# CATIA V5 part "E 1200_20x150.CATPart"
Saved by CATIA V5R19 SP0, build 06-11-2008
Definition: E 1200_20x150
Nomenclature: E 1200_20x150
Description: PART--DESC
Material "Steel": density 7860 kg/m3, Young's modulus 2e+11 Pa, Poisson ratio 0.266, thermal expansion 1.17e-05 1/K
Bounding box of the stored display mesh (mm): x 205 to 235, y -244 to -214, z -29.5 to 140.5
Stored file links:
  G:\UTB\Kombinované\Bakalářská práce\Catia\FORMA\E 1200_20x150.CATPart
  D:\Aplikace\CATIA\Nová složka\win_b64\startup\materials\Catalog.CATMaterial
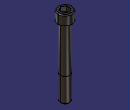
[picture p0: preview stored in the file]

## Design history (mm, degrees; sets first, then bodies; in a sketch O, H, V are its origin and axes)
Body1 "E 1200_20x150" (main body)
  Solid1: solid without history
